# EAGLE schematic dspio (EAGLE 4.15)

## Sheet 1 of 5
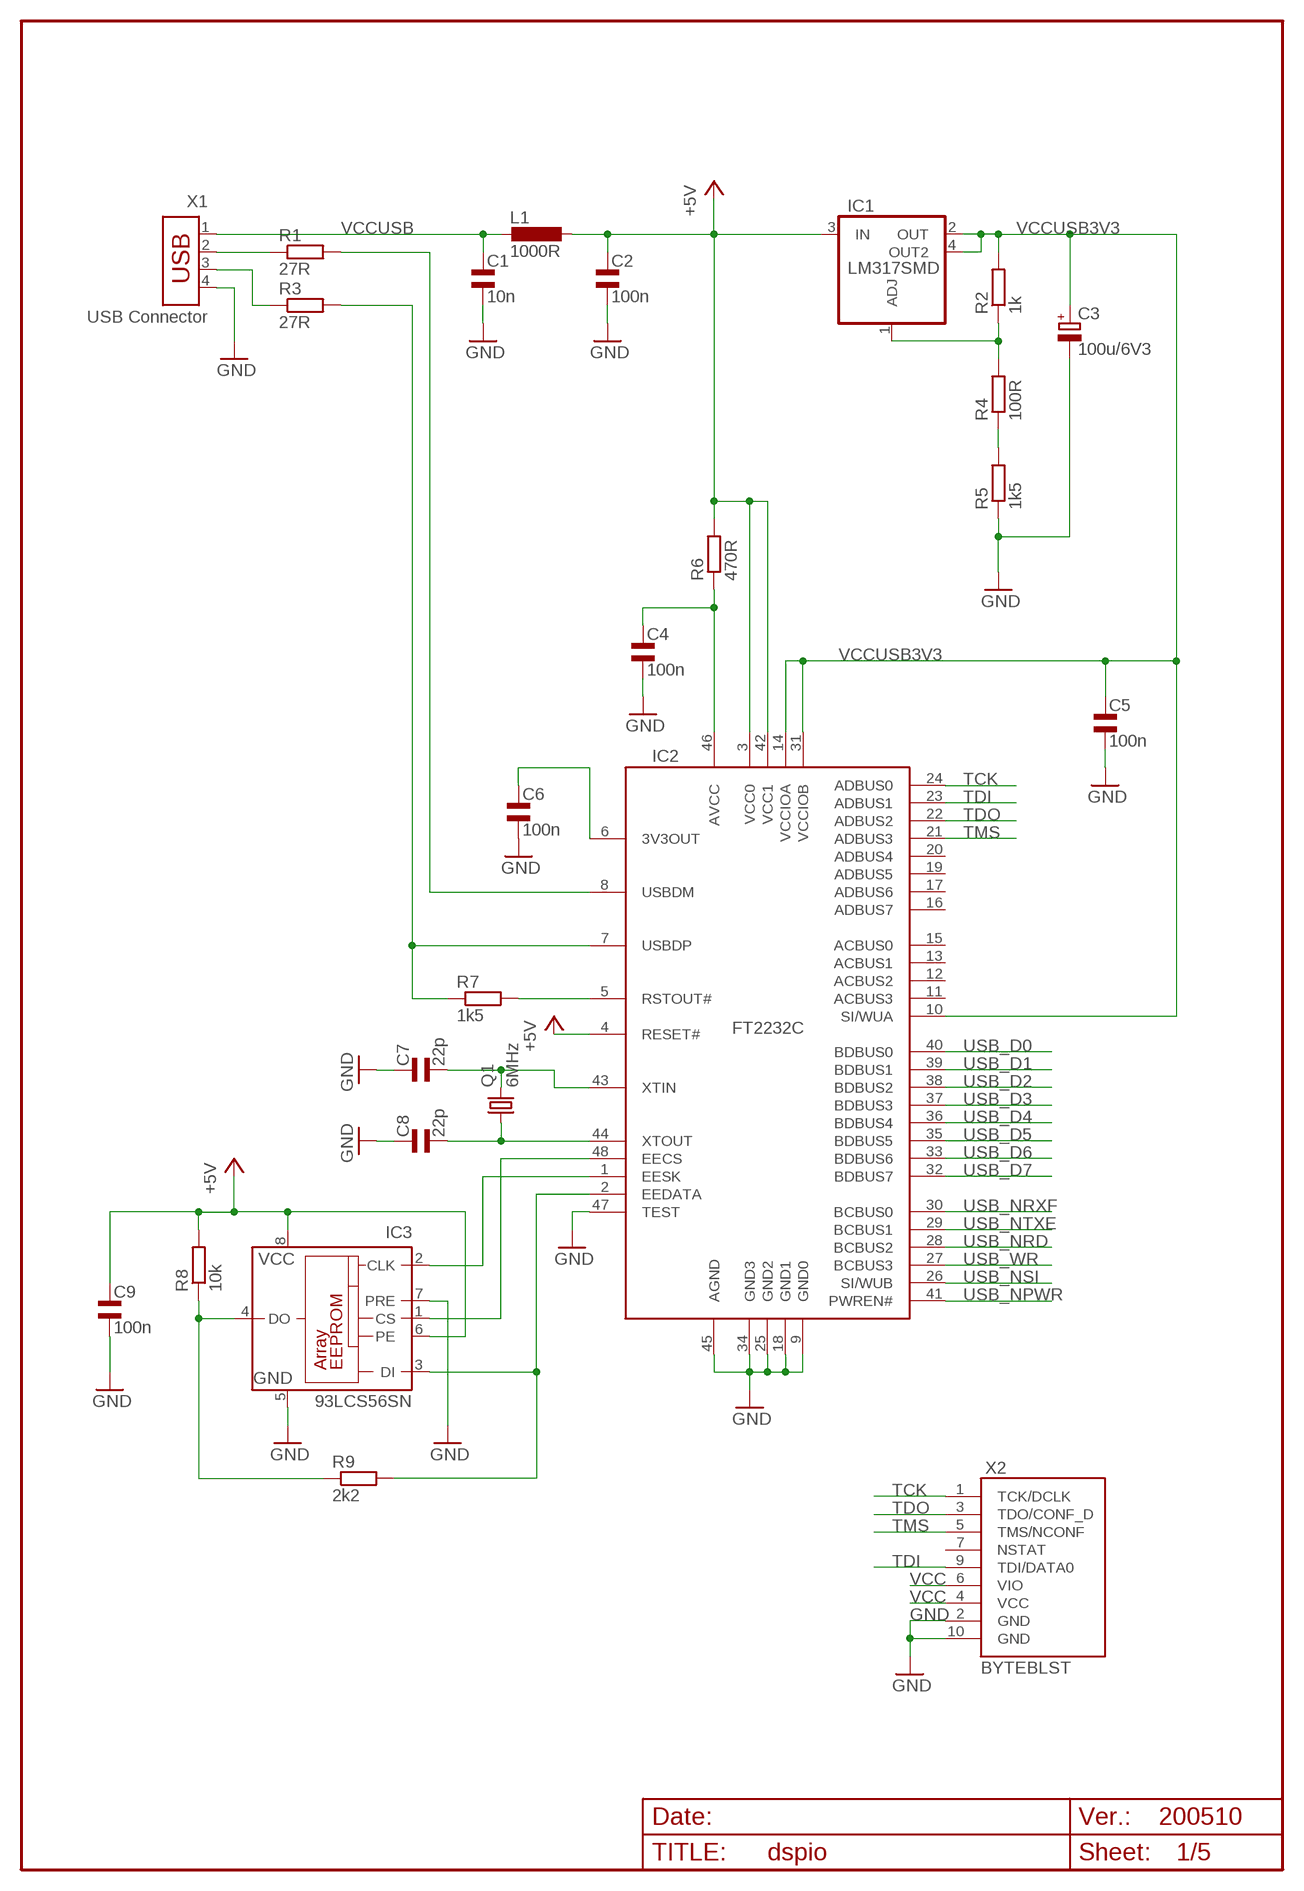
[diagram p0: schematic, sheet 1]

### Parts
C1  10n  C0805  [0805]
C2  100n  C0805  [0805]
C3  100u/6V3  CPOL-EUD  [PANASONIC_D]
C4  100n  C0805  [0805]
C5  100n  C0805  [0805]
C6  100n  C0805  [0805]
C7  22p  C0805  [0805]
C8  22p  C0805  [0805]
C9  100n  C0805  [0805]
IC1  LM317SMD  [SOT223]
IC2  FT2232C  [LQFP]
IC3  93LCS56SN  [SO-08]
L1  1000R  L1206  [1206]
Q1  6MHz  HC49U-V  [HC49U-V]
R1  27R  R0805  [0805]
R2  1k  R0805  [0805]
R3  27R  R0805  [0805]
R4  100R  R0805  [0805]
R5  1k5  R0805  [0805]
R6  470R  R0805  [0805]
R7  1k5  R0805  [0805]
R8  10k  R0805  [0805]
R9  2k2  R0805  [0805]
X1  USB Connector  USB-787780"  [USB-B]
X2  BYTEBLST  [BYTEBLST]

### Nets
+5V: C2.2 C9.2 IC1.3(IN) IC2.3(VCC0) IC2.4(RESET#) IC2.42(VCC1) IC3.6(PE) IC3.8(VCC) L1.1 R6.2 R8.2
GND: C1.1 C2.1 C3.- C4.1 C5.1 C6.1 C7.2 C8.2 C9.1 IC2.9(GND0) IC2.18(GND1) IC2.25(GND2) IC2.34(GND3) IC2.45(AGND) IC2.47(TEST) IC3.5(GND) IC3.7(PRE) R5.1 X1.4 X2.2(GND) X2.10(GND) ; also sheet 2,3,4,5
N$1: C7.1 IC2.43(XTIN) Q1.2
N$2: C8.1 IC2.44(XTOUT) Q1.1
N$3: R3.1 X1.3
N$4: R1.1 X1.2
N$5: C6.2 IC2.6(3V3OUT)
N$6: IC2.8(USBDM) R1.2
N$7: IC2.7(USBDP) R3.2 R7.1
N$8: IC2.5(RSTOUT#) R7.2
N$9: C4.2 IC2.46(AVCC) R6.1
N$10: IC2.48(EECS) IC3.1(CS)
N$11: IC2.1(EESK) IC3.2(CLK)
N$12: IC2.2(EEDATA) IC3.3(DI) R9.2
N$13: IC3.4(DO) R8.1 R9.1
N$17: IC1.1(ADJ) R2.1 R4.2
N$45: R4.1 R5.2
TCK: IC2.24(ADBUS0) X2.1(TCK/DCLK)
TDI: IC2.23(ADBUS1) X2.9(TDI/DATA0)
TDO: IC2.22(ADBUS2) X2.3(TDO/CONF_D)
TMS: IC2.21(ADBUS3) X2.5(TMS/NCONF)
USB_D0: IC2.40(BDBUS0) ; also sheet 2
USB_D1: IC2.39(BDBUS1) ; also sheet 2
USB_D2: IC2.38(BDBUS2) ; also sheet 2
USB_D3: IC2.37(BDBUS3) ; also sheet 2
USB_D4: IC2.36(BDBUS4) ; also sheet 2
USB_D5: IC2.35(BDBUS5) ; also sheet 2
USB_D6: IC2.33(BDBUS6) ; also sheet 2
USB_D7: IC2.32(BDBUS7) ; also sheet 2
USB_NPWR: IC2.41(PWREN#) ; also sheet 2
USB_NRD: IC2.28(BCBUS2) ; also sheet 2
USB_NRXF: IC2.30(BCBUS0) ; also sheet 2
USB_NSI: IC2.26(SI/WUB) ; also sheet 2
USB_NTXE: IC2.29(BCBUS1) ; also sheet 2
USB_WR: IC2.27(BCBUS3) ; also sheet 2
VCC: X2.4(VCC) X2.6(VIO) ; also sheet 2,3,4,5
VCCUSB: C1.2 L1.2 X1.1
VCCUSB3V3: C3.+ C5.2 IC1.2(OUT) IC1.4(OUT2) IC2.10(SI/WUA) IC2.14(VCCIOA) IC2.31(VCCIOB) R2.2 ; also sheet 2
Unconnected: IC2.11(ACBUS3) IC2.12(ACBUS2) IC2.13(ACBUS1) IC2.15(ACBUS0) IC2.16(ADBUS7) IC2.17(ADBUS6) IC2.19(ADBUS5) IC2.20(ADBUS4) X2.7(NSTAT)

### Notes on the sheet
- 200510

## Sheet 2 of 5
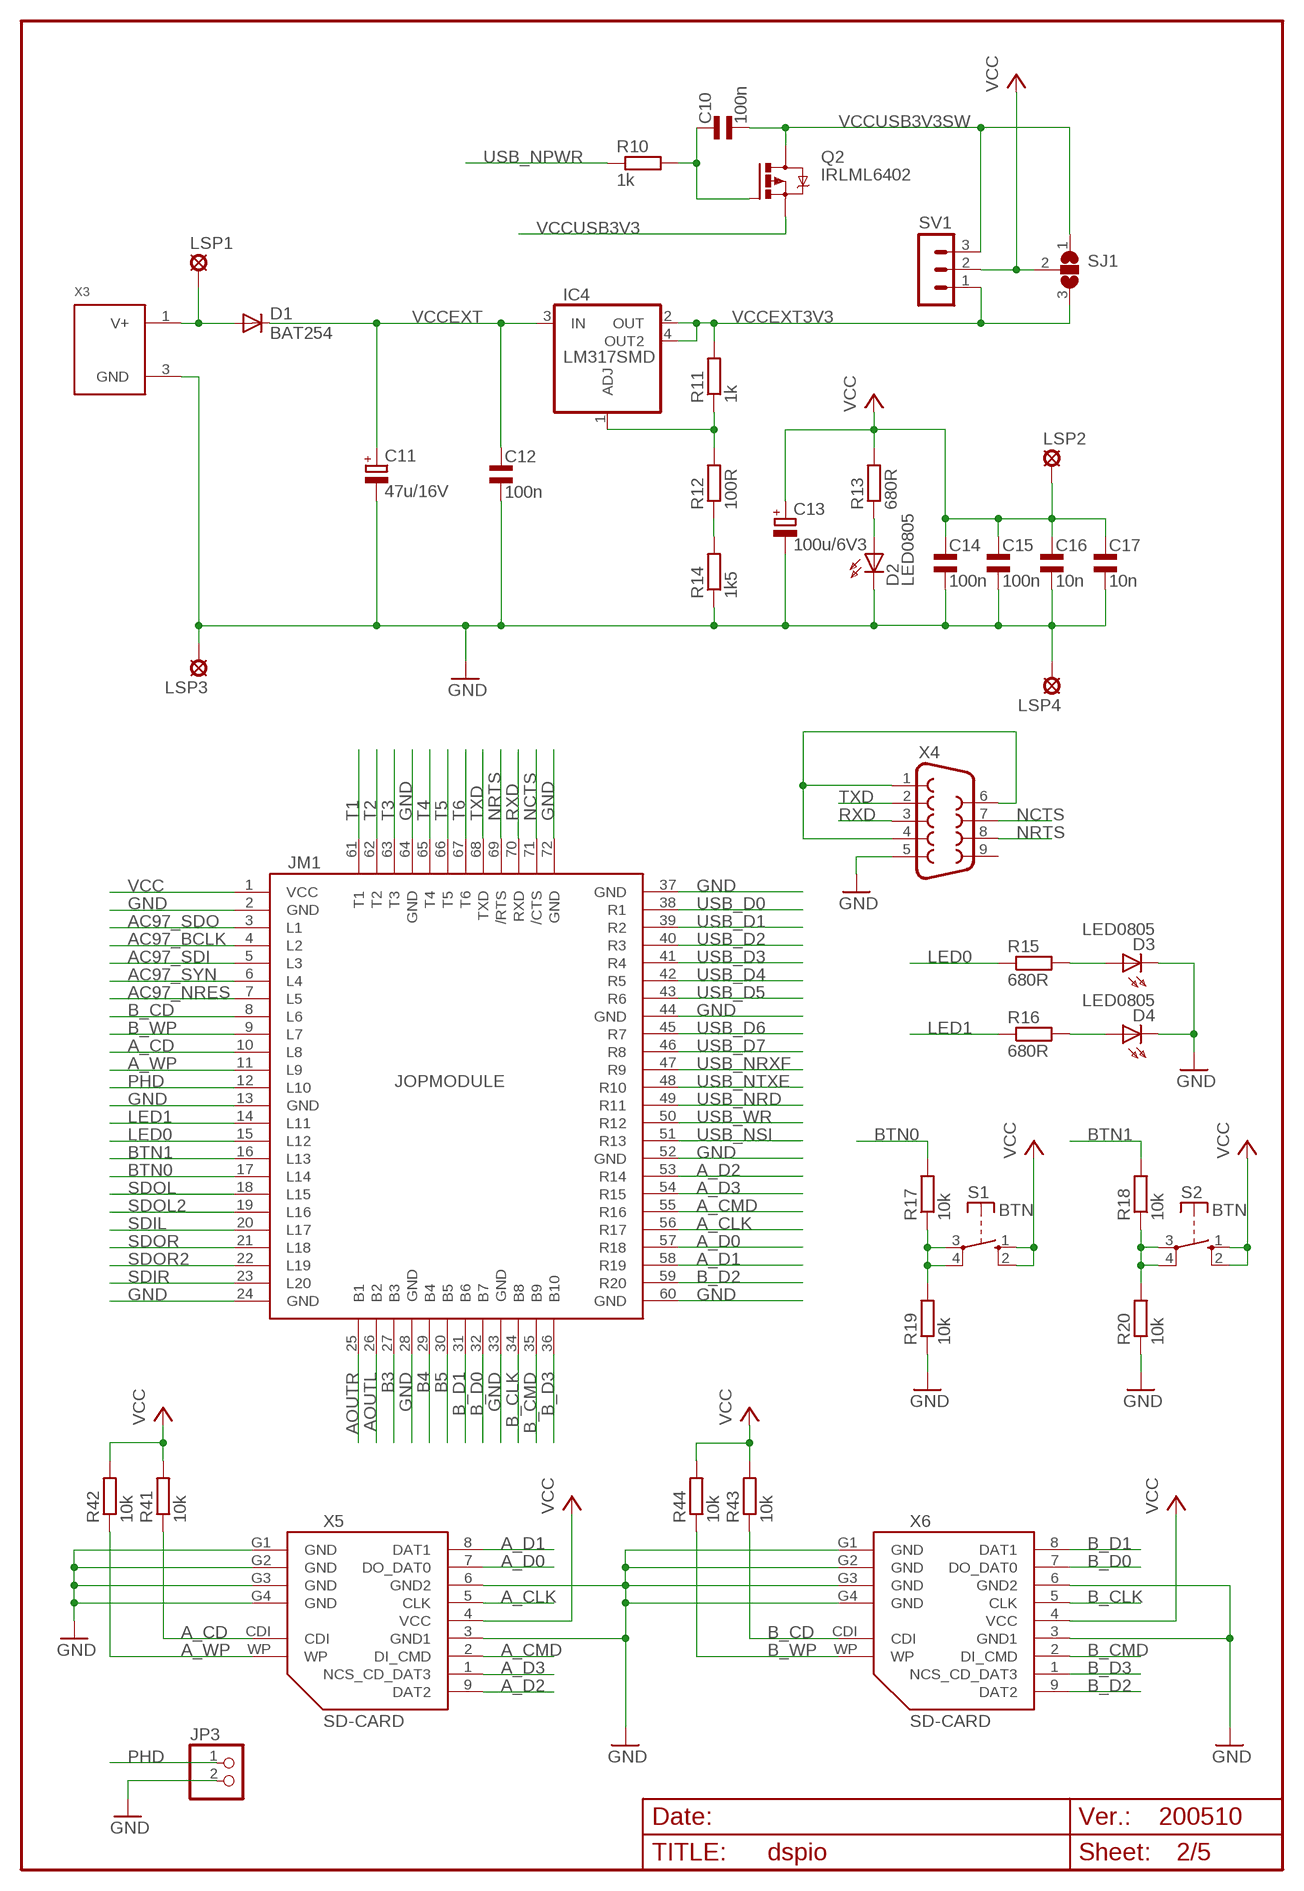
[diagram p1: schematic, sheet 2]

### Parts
C10  100n  C0805  [0805]
C11  47u/16V  CPOL-EUD  [PANASONIC_D]
C12  100n  C0805  [0805]
C13  100u/6V3  CPOL-EUD  [PANASONIC_D]
C14  100n  C0805  [0805]
C15  100n  C0805  [0805]
C16  10n  C0805  [0805]
C17  10n  C0805  [0805]
D1  BAT254  D0805  [D0805]
D2  LED0805  [D0805]
D3  LED0805  [D0805]
D4  LED0805  [D0805]
IC4  LM317SMD  [SOT223]
JM1  JOPMODULE  [JOPMODULE]
JP3  PINHD-1X2  [1X02]
LSP1  LSP10  [LSP10]
LSP2  LSP10  [LSP10]
LSP3  LSP10  [LSP10]
LSP4  LSP10  [LSP10]
Q2  IRLML6402  IRLML5203  [MICRO3]
R10  1k  R0805  [0805]
R11  1k  R0805  [0805]
R12  100R  R0805  [0805]
R13  680R  R0805  [0805]
R14  1k5  R0805  [0805]
R15  680R  R0805  [0805]
R16  680R  R0805  [0805]
R17  10k  R0805  [0805]
R18  10k  R0805  [0805]
R19  10k  R0805  [0805]
R20  10k  R0805  [0805]
R41  10k  R0805  [0805]
R42  10k  R0805  [0805]
R43  10k  R0805  [0805]
R44  10k  R0805  [0805]
S1  BTN  [BTN]
S2  BTN  [BTN]
SJ1  SJ2W  [SJ_2]
SV1  MA03-1  [MA03-1]
X3  DCCON  [DCCON]
X4  F09HP  [F09HP]
X5  SD-CARD  [SD-CARD]
X6  SD-CARD  [SD-CARD]

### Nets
A_CD: JM1.10(L8) R41.1 X5.CDI
A_CLK: JM1.56(R17) X5.5(CLK)
A_CMD: JM1.55(R16) X5.2(DI_CMD)
A_D0: JM1.57(R18) X5.7(DO_DAT0)
A_D1: JM1.58(R19) X5.8(DAT1)
A_D2: JM1.53(R14) X5.9(DAT2)
A_D3: JM1.54(R15) X5.1(NCS_CD_DAT3)
A_WP: JM1.11(L9) R42.1 X5.WP
AC97_BCLK: JM1.4(L2) ; also sheet 4
AC97_NRES: JM1.7(L5) ; also sheet 4
AC97_SDI: JM1.5(L3) ; also sheet 4
AC97_SDO: JM1.3(L1) ; also sheet 4
AC97_SYN: JM1.6(L4) ; also sheet 4
AOUTL: JM1.26(B2) ; also sheet 3
AOUTR: JM1.25(B1) ; also sheet 3
B3: JM1.27(B3) ; also sheet 5
B4: JM1.29(B4) ; also sheet 5
B5: JM1.30(B5) ; also sheet 5
B_CD: JM1.8(L6) R43.1 X6.CDI
B_CLK: JM1.34(B8) X6.5(CLK)
B_CMD: JM1.35(B9) X6.2(DI_CMD)
B_D0: JM1.32(B7) X6.7(DO_DAT0)
B_D1: JM1.31(B6) X6.8(DAT1)
B_D2: JM1.59(R20) X6.9(DAT2)
B_D3: JM1.36(B10) X6.1(NCS_CD_DAT3)
B_WP: JM1.9(L7) R44.1 X6.WP
BTN0: JM1.17(L14) R17.2
BTN1: JM1.16(L13) R18.2
GND: C11.- C12.1 C13.- C14.1 C15.1 C16.1 C17.1 D2.2(C) D3.2(C) D4.2(C) JM1.2(GND) JM1.13(GND) JM1.24(GND) JM1.28(GND) JM1.33(GND) JM1.37(GND) JM1.44(GND) JM1.52(GND) JM1.60(GND) JM1.64(GND) JM1.72(GND) JP3.2 LSP3.MP LSP4.MP R14.1 R19.1 R20.1 X3.3(GND) X4.5 X5.3(GND1) X5.6(GND2) X5.G1(GND) X5.G2(GND) X5.G3(GND) X5.G4(GND) X6.3(GND1) X6.6(GND2) X6.G1(GND) X6.G2(GND) X6.G3(GND) X6.G4(GND) ; also sheet 1,3,4,5
LED0: JM1.15(L12) R15.1
LED1: JM1.14(L11) R16.1
N$14: C10.2 Q2.1(G) R10.2
N$18: R17.1 R19.2 S1.3(P) S1.4(P)
N$19: R18.1 R20.2 S2.3(P) S2.4(P)
N$21: D3.1(A) R15.2
N$22: D4.1(A) R16.2
N$87: D2.1(A) R13.1
N$88: R12.1 R14.2
N$91: IC4.1(ADJ) R11.1 R12.2
N$92: D1.1(A) LSP1.MP X3.1(V+)
N$94: X4.1 X4.4 X4.6
NCTS: JM1.71(/CTS) X4.7
NRTS: JM1.69(/RTS) X4.8
PHD: JM1.12(L10) JP3.1
RXD: JM1.70(RXD) X4.3
SDIL: JM1.20(L17) ; also sheet 3
SDIR: JM1.23(L20) ; also sheet 3
SDOL: JM1.18(L15) ; also sheet 3
SDOL2: JM1.19(L16) ; also sheet 3
SDOR: JM1.21(L18) ; also sheet 3
SDOR2: JM1.22(L19) ; also sheet 3
T1: JM1.61(T1) ; also sheet 5
T2: JM1.62(T2) ; also sheet 5
T3: JM1.63(T3) ; also sheet 5
T4: JM1.65(T4) ; also sheet 5
T5: JM1.66(T5) ; also sheet 5
T6: JM1.67(T6) ; also sheet 5
TXD: JM1.68(TXD) X4.2
USB_D0: JM1.38(R1) ; also sheet 1
USB_D1: JM1.39(R2) ; also sheet 1
USB_D2: JM1.40(R3) ; also sheet 1
USB_D3: JM1.41(R4) ; also sheet 1
USB_D4: JM1.42(R5) ; also sheet 1
USB_D5: JM1.43(R6) ; also sheet 1
USB_D6: JM1.45(R7) ; also sheet 1
USB_D7: JM1.46(R8) ; also sheet 1
USB_NPWR: R10.1 ; also sheet 1
USB_NRD: JM1.49(R11) ; also sheet 1
USB_NRXF: JM1.47(R9) ; also sheet 1
USB_NSI: JM1.51(R13) ; also sheet 1
USB_NTXE: JM1.48(R10) ; also sheet 1
USB_WR: JM1.50(R12) ; also sheet 1
VCC: C13.+ C14.2 C15.2 C16.2 C17.2 JM1.1(VCC) LSP2.MP R13.2 R41.2 R42.2 R43.2 R44.2 S1.1(S) S1.2(S) S2.1(S) S2.2(S) SJ1.2 SV1.2 X5.4(VCC) X6.4(VCC) ; also sheet 1,3,4,5
VCCEXT: C11.+ C12.2 D1.2(C) IC4.3(IN)
VCCEXT3V3: IC4.2(OUT) IC4.4(OUT2) R11.2 SJ1.3 SV1.1
VCCUSB3V3: Q2.2(S) ; also sheet 1
VCCUSB3V3SW: C10.1 Q2.3(D) SJ1.1 SV1.3
Unconnected: X4.9

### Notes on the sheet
- 200510

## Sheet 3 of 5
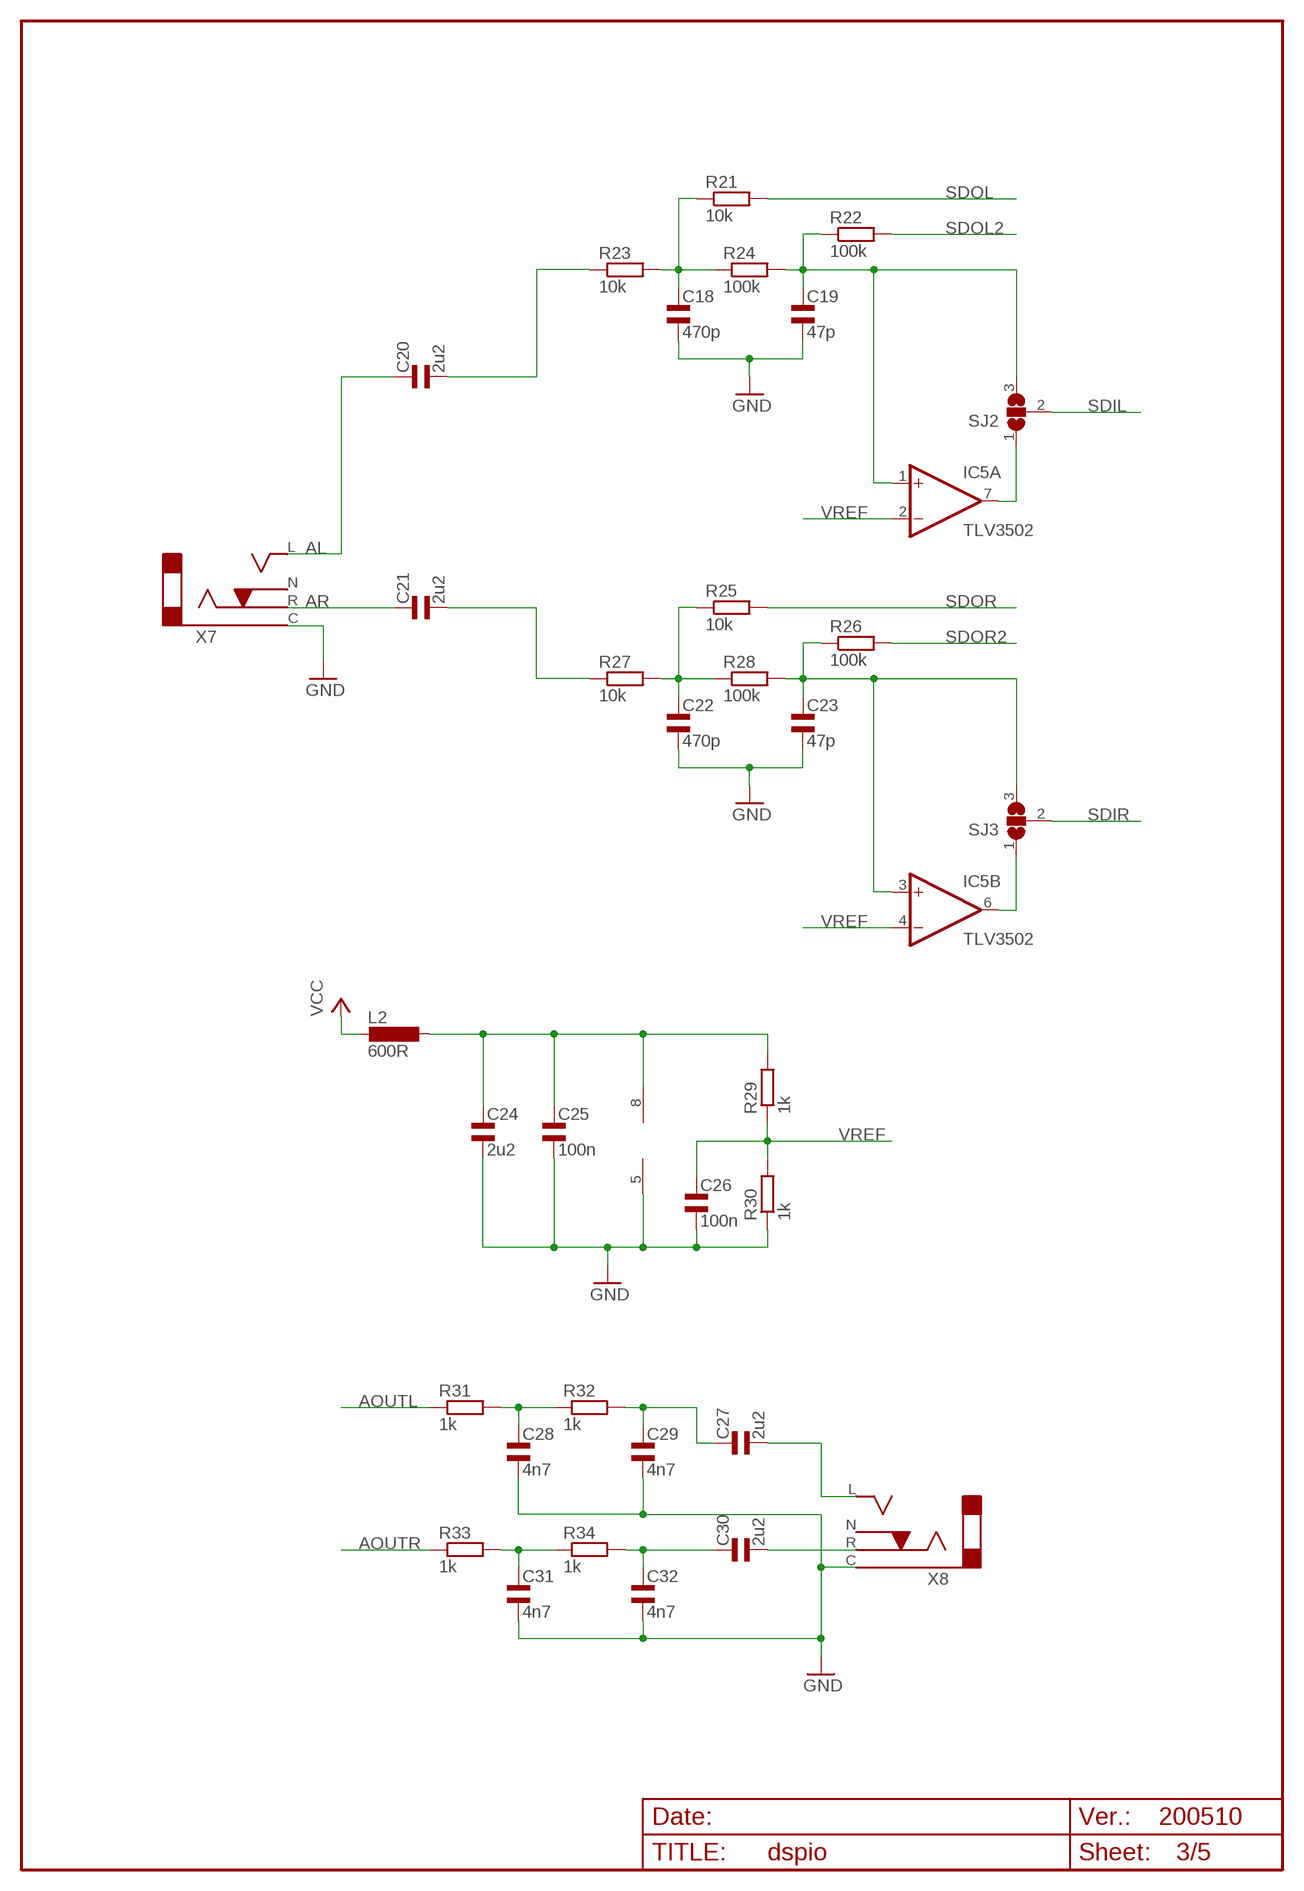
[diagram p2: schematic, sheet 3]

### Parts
C18  470p  C0805  [0805]
C19  47p  C0805  [0805]
C20  2u2  C1206  [1206]
C21  2u2  C1206  [1206]
C22  470p  C0805  [0805]
C23  47p  C0805  [0805]
C24  2u2  C1206  [1206]
C25  100n  C0805  [0805]
C26  100n  C0805  [0805]
C27  2u2  C1206  [1206]
C28  4n7  C0805  [0805]
C29  4n7  C0805  [0805]
C30  2u2  C1206  [1206]
C31  4n7  C0805  [0805]
C32  4n7  C0805  [0805]
IC5  TLV3502  [SOT23-8]
L2  600R  L0805  [0805]
R21  10k  R0805  [0805]
R22  100k  R0805  [0805]
R23  10k  R0805  [0805]
R24  100k  R0805  [0805]
R25  10k  R0805  [0805]
R26  100k  R0805  [0805]
R27  10k  R0805  [0805]
R28  100k  R0805  [0805]
R29  1k  R0805  [0805]
R30  1k  R0805  [0805]
R31  1k  R0805  [0805]
R32  1k  R0805  [0805]
R33  1k  R0805  [0805]
R34  1k  R0805  [0805]
SJ2  SJ2W  [SJ_2]
SJ3  SJ2W  [SJ_2]
X7  STEREO35  [STEREO35]
X8  STEREO35  [STEREO35]

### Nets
AL: C20.2 X7.L
AOUTL: R31.1 ; also sheet 2
AOUTR: R33.1 ; also sheet 2
AR: C21.2 X7.R
COMPOL: IC5.7(A:OUT) SJ2.1
COMPOL1: IC5.6(B:OUT) SJ3.1
GND: C18.1 C19.1 C22.1 C23.1 C24.1 C25.1 C26.1 C28.1 C29.1 C31.1 C32.1 IC5.5(P:V-) R30.1 X7.C X8.C ; also sheet 1,2,4,5
N$41: C18.2 R21.1 R23.2 R24.1
N$48: C24.2 C25.2 IC5.8(P:V+) L2.1 R29.2
N$60: C19.2 IC5.1(A:+IN) R22.1 R24.2 SJ2.3
N$62: C22.2 R25.1 R27.2 R28.1
N$63: C28.2 R31.2 R32.1
N$64: C27.2 C29.2 R32.2
N$65: C27.1 X8.L
N$66: C30.1 X8.R
N$67: C30.2 C32.2 R34.2
N$68: C31.2 R33.2 R34.1
N$69: C23.2 IC5.3(B:+IN) R26.1 R28.2 SJ3.3
N$70: C20.1 R23.1
N$71: C21.1 R27.1
SDIL: SJ2.2 ; also sheet 2
SDIR: SJ3.2 ; also sheet 2
SDOL: R21.2 ; also sheet 2
SDOL2: R22.2 ; also sheet 2
SDOR: R25.2 ; also sheet 2
SDOR2: R26.2 ; also sheet 2
VCC: L2.2 ; also sheet 1,2,4,5
VREF: C26.2 IC5.2(A:-IN) IC5.4(B:-IN) R29.1 R30.2
Unconnected: X7.N X8.N

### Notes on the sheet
- 200510

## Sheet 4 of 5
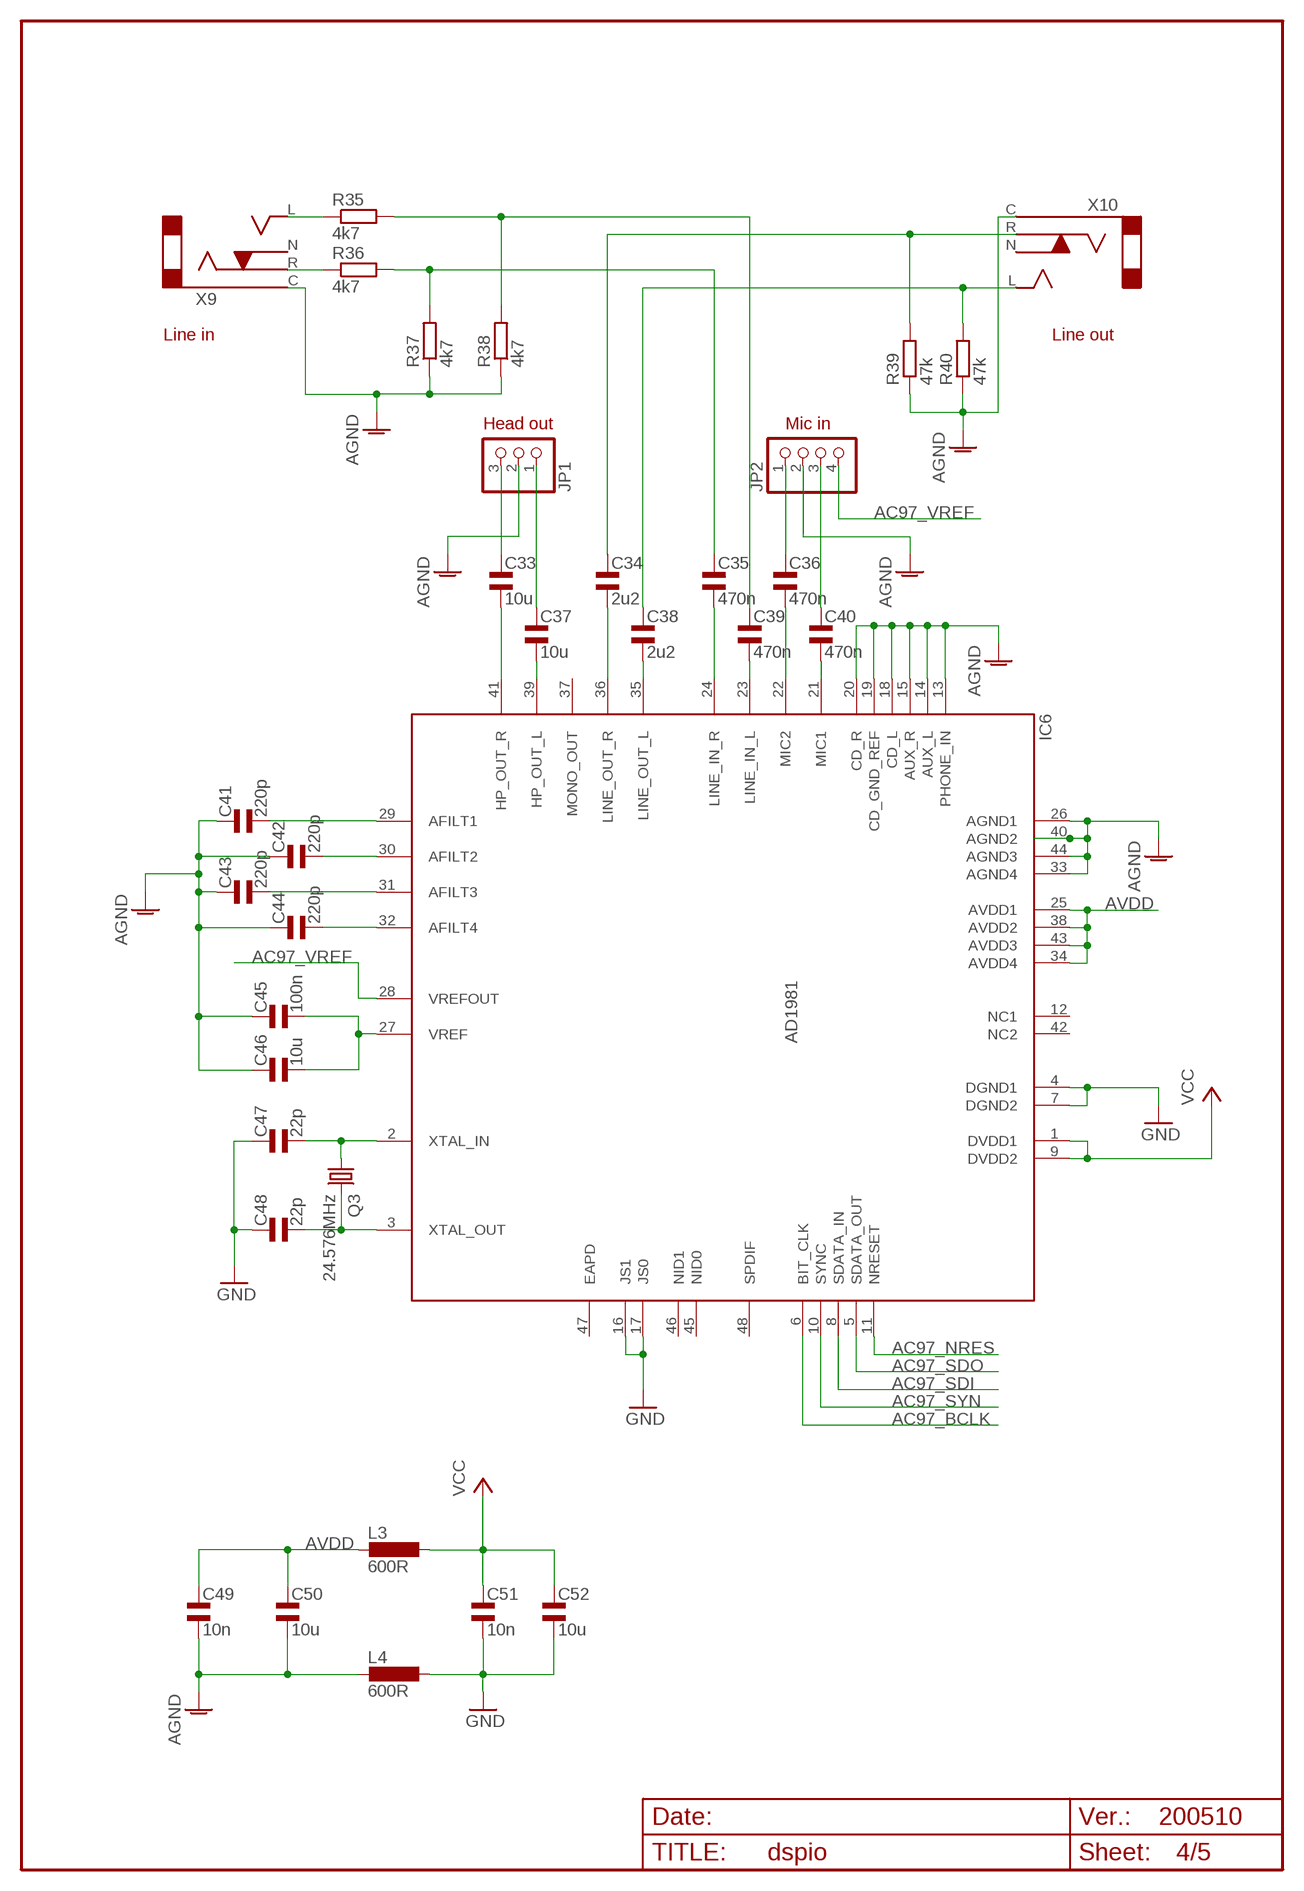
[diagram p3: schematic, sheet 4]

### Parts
C33  10u  C1210  [1210]
C34  2u2  C1206  [1206]
C35  470n  C0805  [0805]
C36  470n  C0805  [0805]
C37  10u  C1210  [1210]
C38  2u2  C1206  [1206]
C39  470n  C0805  [0805]
C40  470n  C0805  [0805]
C41  220p  C0805  [0805]
C42  220p  C0805  [0805]
C43  220p  C0805  [0805]
C44  220p  C0805  [0805]
C45  100n  C0805  [0805]
C46  10u  C1210  [1210]
C47  22p  C0805  [0805]
C48  22p  C0805  [0805]
C49  10n  C0805  [0805]
C50  10u  C1210  [1210]
C51  10n  C0805  [0805]
C52  10u  C1210  [1210]
IC6  AD1981  [QFP48]
JP1  PINHD-1X3  [1X03]
JP2  PINHD-1X4  [1X04]
L3  600R  L0805  [0805]
L4  600R  L0805  [0805]
Q3  24.576MHz  HC49U-V  [HC49U-V]
R35  4k7  R0805  [0805]
R36  4k7  R0805  [0805]
R37  4k7  R0805  [0805]
R38  4k7  R0805  [0805]
R39  47k  R0805  [0805]
R40  47k  R0805  [0805]
X9  STEREO35  [STEREO35]
X10  STEREO35  [STEREO35]

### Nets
AC97_BCLK: IC6.6(BIT_CLK) ; also sheet 2
AC97_NRES: IC6.11(NRESET) ; also sheet 2
AC97_SDI: IC6.8(SDATA_IN) ; also sheet 2
AC97_SDO: IC6.5(SDATA_OUT) ; also sheet 2
AC97_SYN: IC6.10(SYNC) ; also sheet 2
AC97_VREF: IC6.28(VREFOUT) JP2.4
AGND: C41.2 C42.2 C43.2 C44.2 C45.2 C46.2 C49.1 C50.1 IC6.13(PHONE_IN) IC6.14(AUX_L) IC6.15(AUX_R) IC6.18(CD_L) IC6.19(CD_GND_REF) IC6.20(CD_R) IC6.26(AGND1) IC6.33(AGND4) IC6.40(AGND2) IC6.44(AGND3) JP1.2 JP2.2 L4.2 R37.1 R38.1 R39.1 R40.1 X9.C X10.C
AVDD: C49.2 C50.2 IC6.25(AVDD1) IC6.34(AVDD4) IC6.38(AVDD2) IC6.43(AVDD3) L3.2
GND: C47.2 C48.2 C51.1 C52.1 IC6.4(DGND1) IC6.7(DGND2) IC6.16(JS1) IC6.17(JS0) L4.1 ; also sheet 1,2,3,5
N$16: C40.1 IC6.21(MIC1)
N$20: C36.1 IC6.22(MIC2)
N$23: C39.1 IC6.23(LINE_IN_L)
N$24: C35.1 IC6.24(LINE_IN_R)
N$25: C38.1 IC6.35(LINE_OUT_L)
N$26: C34.1 IC6.36(LINE_OUT_R)
N$27: C37.1 IC6.39(HP_OUT_L)
N$28: C33.1 IC6.41(HP_OUT_R)
N$29: C33.2 JP1.3
N$30: C36.2 JP2.1
N$31: C34.2 R39.2 X10.R
N$32: C38.2 R40.2 X10.L
N$33: R35.1 X9.L
N$34: R36.1 X9.R
N$35: C37.2 JP1.1
N$36: C40.2 JP2.3
N$37: C41.1 IC6.29(AFILT1)
N$38: C42.1 IC6.30(AFILT2)
N$39: C43.1 IC6.31(AFILT3)
N$40: C44.1 IC6.32(AFILT4)
N$42: C45.1 C46.1 IC6.27(VREF)
N$43: C47.1 IC6.2(XTAL_IN) Q3.1
N$44: C48.1 IC6.3(XTAL_OUT) Q3.2
N$46: C35.2 R36.2 R37.2
N$47: C39.2 R35.2 R38.2
VCC: C51.2 C52.2 IC6.1(DVDD1) IC6.9(DVDD2) L3.1 ; also sheet 1,2,3,5
Unconnected: IC6.12(NC1) IC6.37(MONO_OUT) IC6.42(NC2) IC6.45(NID0) IC6.46(NID1) IC6.47(EAPD) IC6.48(SPDIF) X9.N X10.N

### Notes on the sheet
- Line in | Line out
- Head out | Mic in
- 200510

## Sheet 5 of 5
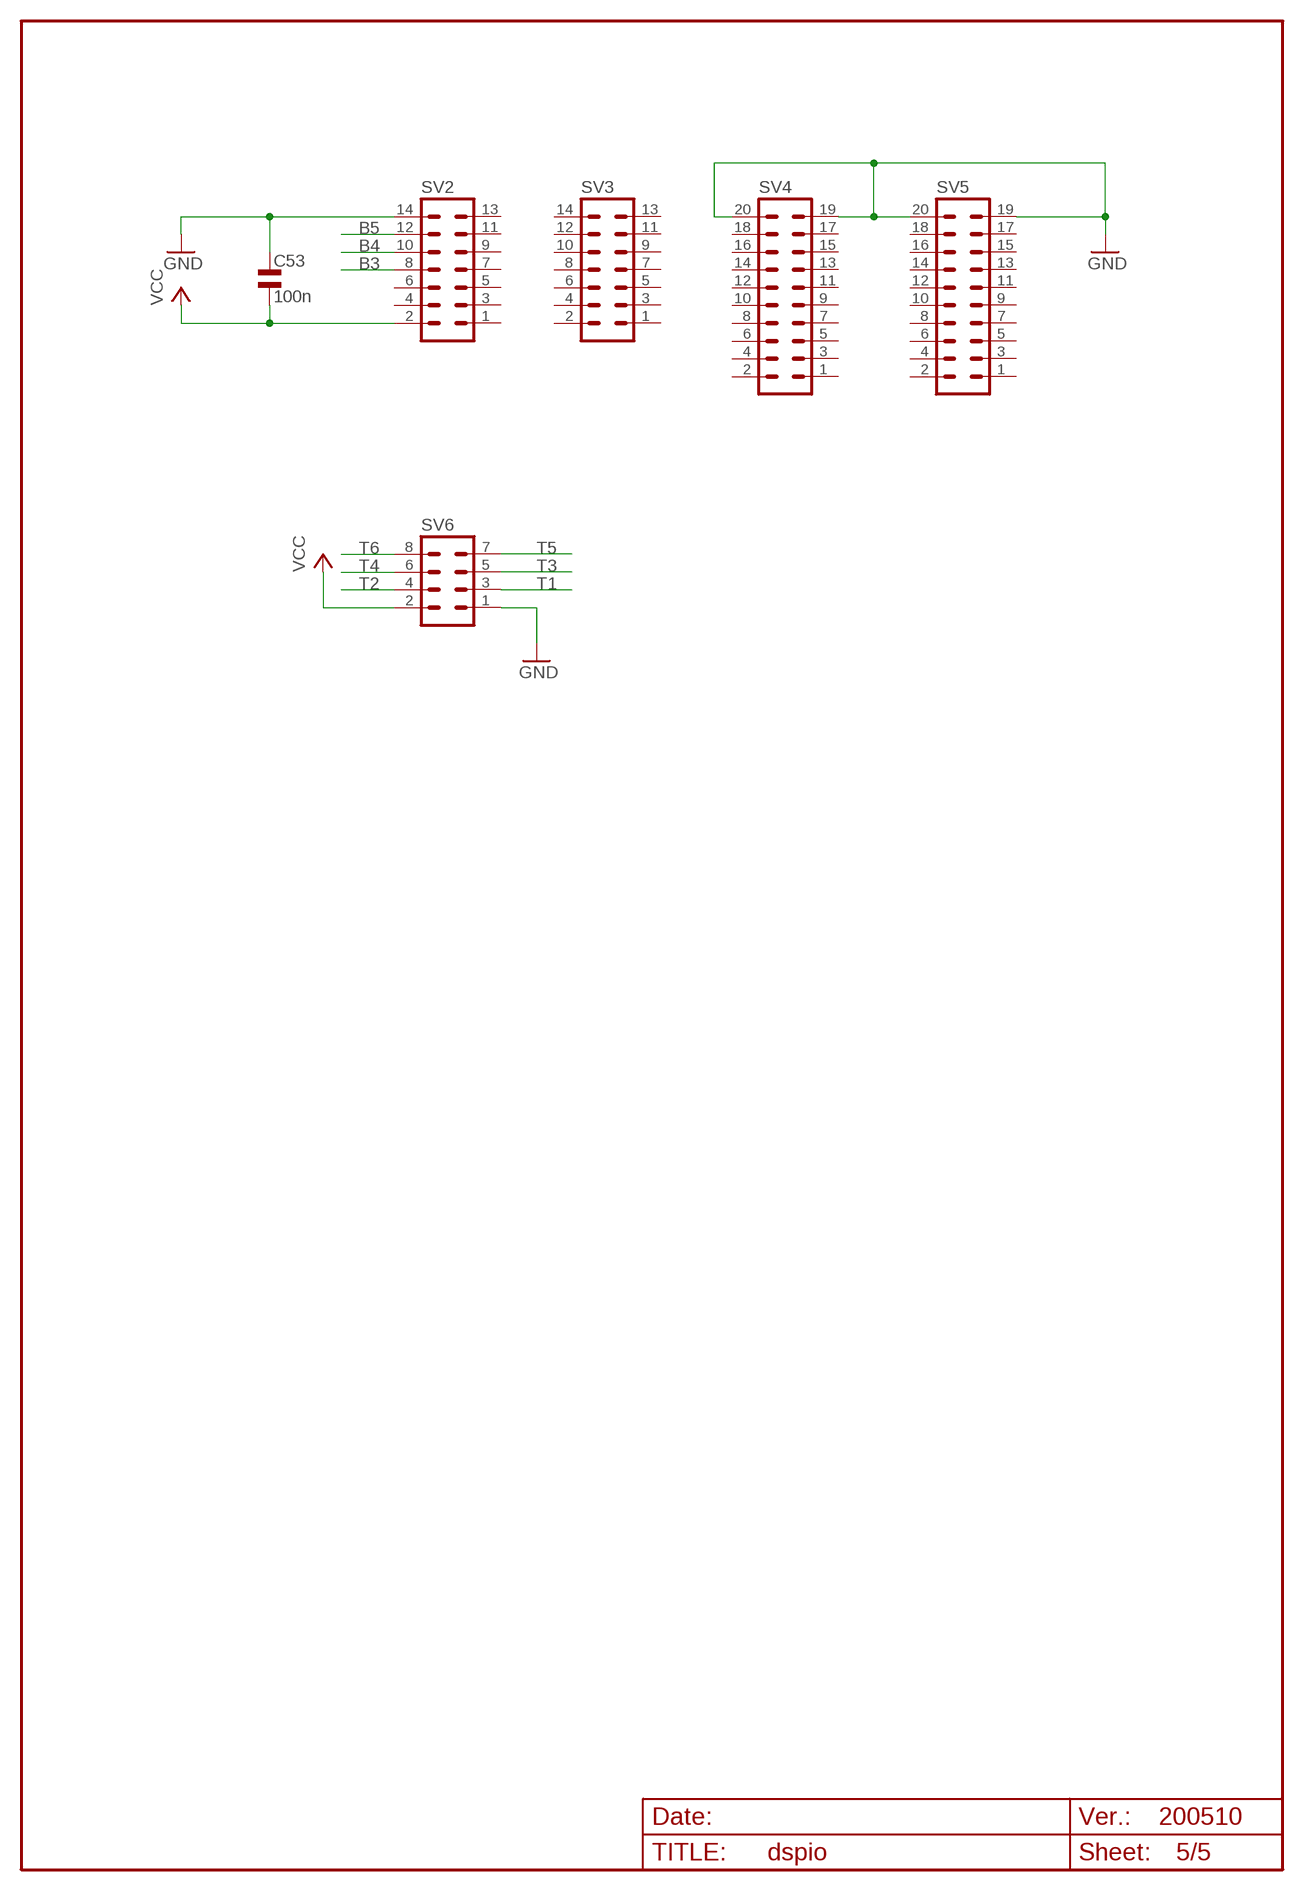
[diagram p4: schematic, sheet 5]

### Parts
C53  100n  C0805  [0805]
SV2  MA07-2  [MA07-2]
SV3  MA07-2  [MA07-2]
SV4  MA10-2  [MA10-2]
SV5  MA10-2  [MA10-2]
SV6  MA04-2  [MA04-2]

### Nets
B3: SV2.8 ; also sheet 2
B4: SV2.10 ; also sheet 2
B5: SV2.12 ; also sheet 2
GND: C53.2 SV2.14 SV4.19 SV4.20 SV5.19 SV5.20 SV6.1 ; also sheet 1,2,3,4
T1: SV6.3 ; also sheet 2
T2: SV6.4 ; also sheet 2
T3: SV6.5 ; also sheet 2
T4: SV6.6 ; also sheet 2
T5: SV6.7 ; also sheet 2
T6: SV6.8 ; also sheet 2
VCC: C53.1 SV2.2 SV6.2 ; also sheet 1,2,3,4
Unconnected: SV2.1 SV2.3 SV2.4 SV2.5 SV2.6 SV2.7 SV2.9 SV2.11 SV2.13 SV3.1 SV3.2 SV3.3 SV3.4 SV3.5 SV3.6 SV3.7 SV3.8 SV3.9 SV3.10 SV3.11 SV3.12 SV3.13 SV3.14 SV4.1 SV4.2 SV4.3 SV4.4 SV4.5 SV4.6 SV4.7 SV4.8 SV4.9 SV4.10 SV4.11 SV4.12 SV4.13 SV4.14 SV4.15 SV4.16 SV4.17 SV4.18 SV5.1 SV5.2 SV5.3 SV5.4 SV5.5 SV5.6 SV5.7 SV5.8 SV5.9 SV5.10 SV5.11 SV5.12 SV5.13 SV5.14 SV5.15 SV5.16 SV5.17 SV5.18

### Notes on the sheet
- 200510

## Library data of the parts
C1 C2 C4-C10 C12 C14-C19 C22 C23 C25 C26 C28 C29 C31 C32 C35 C36 C39-C45 C47-C49 C51 C53 = MY_EAGLE:C0805
C3 C11 C13 = rcl:CPOL-EU: POLARIZED CAPACITOR, European symbol
C20 C21 C24 C27 C30 C34 C38 = MY_EAGLE:C1206
C33 C37 C46 C50 C52 = MY_EAGLE:C1210
D1 = MY_EAGLE:D0805
D2-D4 = MY_EAGLE:LED0805
IC1 IC4 = MY_EAGLE:LM317SMD
IC2 = ft2232C:FT2232C
IC3 = microchip:93LCS*: EEPROM 2 K/4 K, 2.5 V Microwire with software write protect
IC5 = MY_EAGLE:TLV3502: high speed comperator
IC6 = MY_EAGLE:AD1981
JM1 = MY_EAGLE:JOPMODULE
JP1 = pinhead:PINHD-1X3: PIN HEADER
JP2 = pinhead:PINHD-1X4: PIN HEADER
JP3 = pinhead:PINHD-1X2: PIN HEADER
L1 = MY_EAGLE:L1206
L2-L4 = MY_EAGLE:L0805
LSP1-LSP4 = solpad:LSP10: SOLDER PAD
Q1 Q3 = crystal:HC49U-V: CRYSTAL
Q2 = transistor-power:IRLML5203: HEXFET P-Channel Power MOSFET
R1-R44 = MY_EAGLE:R0805
S1 S2 = MY_EAGLE:BTN
SJ1-SJ3 = jumper:SJ2W: SMD solder JUMPER
SV1 = con-lstb:MA03-1: PIN HEADER
SV2 SV3 = con-lstb:MA07-2: PIN HEADER
SV4 SV5 = con-lstb:MA10-2: PIN HEADER
SV6 = con-lstb:MA04-2: PIN HEADER
X1 = con-amp:USB-787780: AMP CONNECTOR
X2 = MY_EAGLE:BYTEBLST
X3 = MY_EAGLE:DCCON
X4 = con-subd:F09: SUB-D
X5 X6 = cyclone:SD-CARD
X7-X10 = MY_EAGLE:STEREO35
